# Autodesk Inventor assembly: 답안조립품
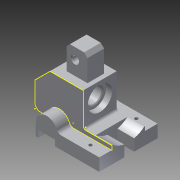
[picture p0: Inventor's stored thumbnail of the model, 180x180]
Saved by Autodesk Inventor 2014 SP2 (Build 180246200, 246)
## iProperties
Created: 2016-11
Part Number: 답안조립품
Document SubType Name: Assembly
Designer: kb
Author: kb
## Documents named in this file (2)
- C:\Users\kb\Desktop\461107v1013\답안조립품.iam
- C:\Users\kb\Desktop\461107v1013\본체.ipt
